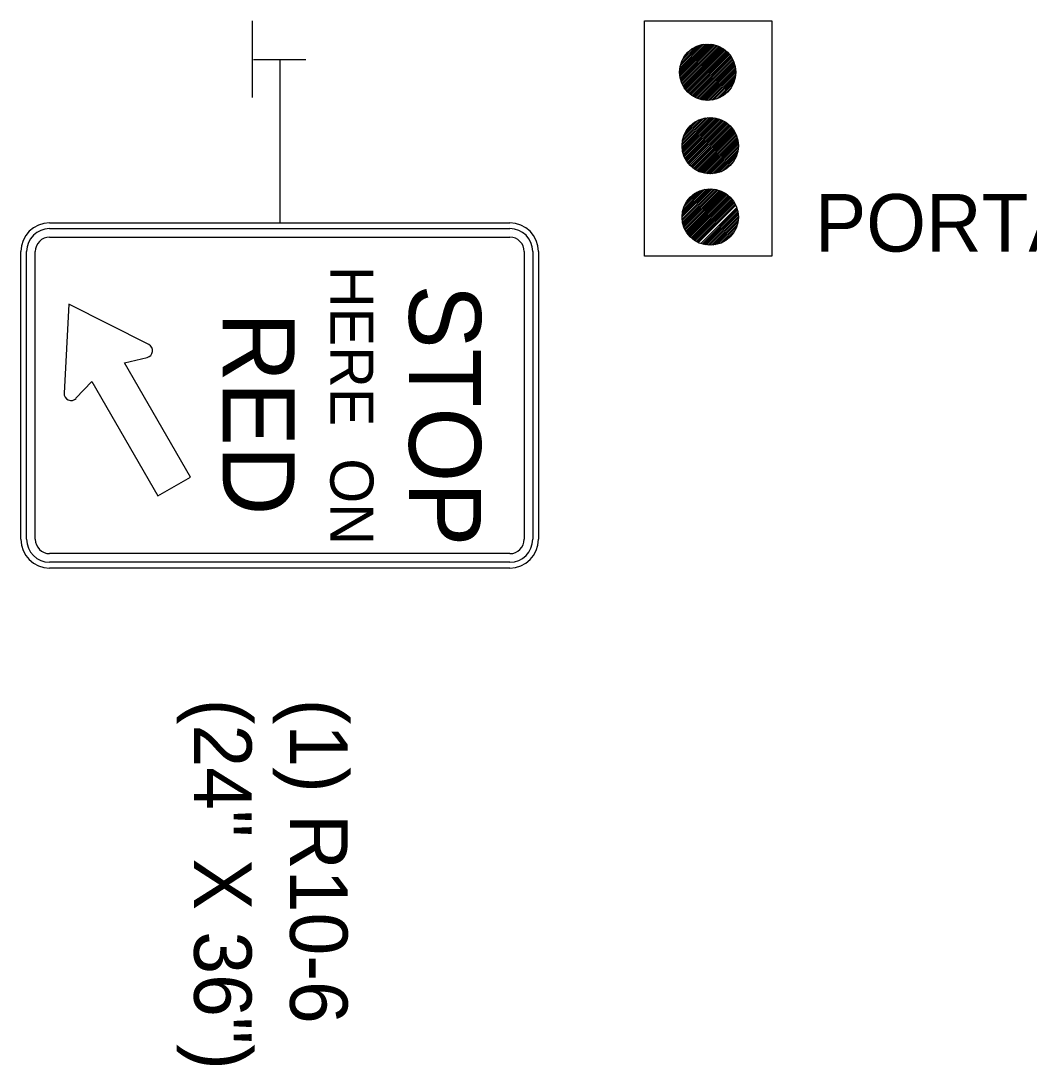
# Model space of a CAD drawing. Extents: x 1925873 to 1930787, y 596452 to 599617.
# Drawn here: x 1928229 to 1928334.2, y 597291.7 to 597400.6 of the extents above; entities that cross this region are included whole.
import ezdxf

# ---------------------------------------------------------------- set-up
doc = ezdxf.new("R2010")
doc.units = 0
for name, color, linetype in [('Default', 7, 'Continuous'), ('P_TC_Signs_Permanent', 7, 'Continuous'), ('R_Border', 7, 'Continuous')]:
    doc.layers.add(name, color=color, linetype=linetype)

msp = doc.modelspace()

# ---------------------------------------------------------------- linework, layer by layer
at = {"layer": 'Default'}
for p, q in [((1928253.15, 597392.62), (1928253.15, 597400.62)), ((1928297.7, 597395.14), (1928300.77, 597398.21)), ((1928297.7, 597395.31), (1928300.59, 597398.21)), ((1928297.7, 597395.5), (1928300.4, 597398.2)), ((1928297.71, 597394.97), (1928300.94, 597398.2)), ((1928297.73, 597394.81), (1928301.1, 597398.18)), ((1928297.73, 597395.71), (1928300.2, 597398.18)), ((1928297.76, 597394.66), (1928301.25, 597398.15)), ((1928297.77, 597395.93), (1928299.98, 597398.14)), ((1928297.8, 597394.51), (1928301.4, 597398.11)), ((1928297.84, 597394.37), (1928301.54, 597398.07)), ((1928297.84, 597396.18), (1928299.73, 597398.07)), ((1928297.88, 597394.24), (1928301.67, 597398.02)), ((1928297.94, 597394.11), (1928301.8, 597397.97)), ((1928297.95, 597396.48), (1928299.43, 597397.96)), ((1928297.99, 597393.98), (1928301.93, 597397.92)), ((1928298.05, 597393.86), (1928302.04, 597397.85)), ((1928298.12, 597393.75), (1928302.16, 597397.79)), ((1928298.17, 597396.87), (1928299.03, 597397.74)), ((1928298.19, 597393.64), (1928302.27, 597397.72)), ((1928298.26, 597393.53), (1928302.38, 597397.64)), ((1928253.27, 597396.6), (1928258.73, 597396.6)), ((1928298.34, 597393.43), (1928302.48, 597397.56)), ((1928298.43, 597393.33), (1928302.58, 597397.48)), ((1928298.51, 597393.24), (1928302.67, 597397.4)), ((1928298.6, 597393.15), (1928302.76, 597397.31)), ((1928298.7, 597393.06), (1928302.85, 597397.21)), ((1928298.8, 597392.98), (1928302.93, 597397.11)), ((1928298.9, 597392.9), (1928303.01, 597397.01)), ((1928299, 597392.82), (1928303.08, 597396.9)), ((1928299.11, 597392.75), (1928303.15, 597396.79)), ((1928299.23, 597392.69), (1928303.22, 597396.68)), ((1928299.35, 597392.63), (1928303.28, 597396.56)), ((1928299.47, 597392.57), (1928303.34, 597396.43)), ((1928299.6, 597392.52), (1928303.39, 597396.31)), ((1928299.74, 597392.47), (1928303.44, 597396.17)), ((1928299.88, 597392.43), (1928303.48, 597396.03)), ((1928300.02, 597392.39), (1928303.51, 597395.89)), ((1928300.17, 597392.37), (1928303.54, 597395.73)), ((1928300.33, 597392.35), (1928303.56, 597395.57)), ((1928300.5, 597392.33), (1928303.58, 597395.41)), ((1928300.68, 597392.33), (1928303.58, 597395.23)), ((1928300.87, 597392.34), (1928303.57, 597395.04)), ((1928301.07, 597392.36), (1928303.55, 597394.83)), ((1928301.3, 597392.41), (1928303.5, 597394.61)), ((1928301.55, 597392.47), (1928303.43, 597394.36)), ((1928301.84, 597392.59), (1928303.32, 597394.06)), ((1928302.24, 597392.81), (1928303.1, 597393.66)), ((1928297.96, 597387.65), (1928300.86, 597390.55)), ((1928297.97, 597387.48), (1928301.04, 597390.55)), ((1928297.97, 597387.84), (1928300.67, 597390.54)), ((1928297.98, 597387.31), (1928301.21, 597390.54)), ((1928298, 597387.15), (1928301.37, 597390.52)), ((1928298, 597388.05), (1928300.47, 597390.52)), ((1928298.03, 597387), (1928301.52, 597390.49)), ((1928298.04, 597388.27), (1928300.25, 597390.48)), ((1928298.06, 597386.85), (1928301.67, 597390.45)), ((1928298.11, 597386.71), (1928301.81, 597390.41)), ((1928298.11, 597388.52), (1928300, 597390.41)), ((1928298.15, 597386.58), (1928301.94, 597390.37)), ((1928298.2, 597386.45), (1928302.07, 597390.31)), ((1928298.22, 597388.82), (1928299.7, 597390.3)), ((1928298.26, 597386.32), (1928302.19, 597390.26)), ((1928298.32, 597386.2), (1928302.31, 597390.2)), ((1928298.39, 597386.09), (1928302.43, 597390.13)), ((1928298.44, 597389.21), (1928299.3, 597390.08)), ((1928298.46, 597385.98), (1928302.54, 597390.06)), ((1928298.53, 597385.87), (1928302.65, 597389.98)), ((1928298.61, 597385.77), (1928302.75, 597389.91)), ((1928298.69, 597385.67), (1928302.85, 597389.82)), ((1928298.78, 597385.58), (1928302.94, 597389.74)), ((1928298.87, 597385.49), (1928303.03, 597389.65)), ((1928298.97, 597385.4), (1928303.12, 597389.55)), ((1928299.06, 597385.32), (1928303.2, 597389.45)), ((1928299.17, 597385.24), (1928303.28, 597389.35)), ((1928299.27, 597385.16), (1928303.35, 597389.24)), ((1928299.38, 597385.09), (1928303.42, 597389.13)), ((1928299.5, 597385.03), (1928303.49, 597389.02)), ((1928299.62, 597384.97), (1928303.55, 597388.9)), ((1928299.74, 597384.91), (1928303.61, 597388.78)), ((1928299.87, 597384.86), (1928303.66, 597388.65)), ((1928300.01, 597384.81), (1928303.71, 597388.51)), ((1928300.15, 597384.77), (1928303.75, 597388.37)), ((1928300.29, 597384.74), (1928303.78, 597388.23)), ((1928300.44, 597384.71), (1928303.81, 597388.07)), ((1928300.6, 597384.69), (1928303.83, 597387.91)), ((1928300.77, 597384.67), (1928303.84, 597387.75)), ((1928300.95, 597384.67), (1928303.85, 597387.57)), ((1928301.14, 597384.68), (1928303.84, 597387.38)), ((1928301.34, 597384.7), (1928303.81, 597387.17)), ((1928301.57, 597384.75), (1928303.77, 597386.95)), ((1928301.82, 597384.82), (1928303.7, 597386.7)), ((1928302.11, 597384.93), (1928303.59, 597386.4)), ((1928302.51, 597385.15), (1928303.37, 597386.01)), ((1928297.96, 597380.14), (1928300.94, 597383.11)), ((1928297.97, 597379.96), (1928301.12, 597383.11)), ((1928297.97, 597380.32), (1928300.76, 597383.11)), ((1928297.98, 597380.52), (1928300.56, 597383.09)), ((1928297.99, 597379.8), (1928301.28, 597383.09)), ((1928298.01, 597379.64), (1928301.44, 597383.07)), ((1928298.02, 597380.73), (1928300.35, 597383.06)), ((1928298.04, 597379.49), (1928301.59, 597383.03)), ((1928298.07, 597380.97), (1928300.11, 597383.01)), ((1928298.08, 597379.35), (1928301.73, 597383)), ((1928298.13, 597379.21), (1928301.87, 597382.95)), ((1928298.16, 597381.24), (1928299.84, 597382.91)), ((1928298.17, 597379.08), (1928302, 597382.9)), ((1928298.23, 597378.95), (1928302.13, 597382.85)), ((1928298.29, 597378.83), (1928302.25, 597382.79)), ((1928298.32, 597381.58), (1928299.5, 597382.76)), ((1928298.35, 597378.71), (1928302.37, 597382.73)), ((1928298.42, 597378.6), (1928302.48, 597382.66)), ((1928298.49, 597378.49), (1928302.59, 597382.59)), ((1928298.57, 597378.39), (1928302.69, 597382.51)), ((1928298.65, 597378.29), (1928302.79, 597382.43)), ((1928298.73, 597378.19), (1928302.89, 597382.35)), ((1928298.82, 597378.1), (1928302.98, 597382.26)), ((1928298.91, 597378.01), (1928303.07, 597382.17)), ((1928299.01, 597377.92), (1928303.15, 597382.07)), ((1928299.11, 597377.84), (1928303.24, 597381.97)), ((1928299.21, 597377.77), (1928303.31, 597381.87)), ((1928299.32, 597377.69), (1928303.38, 597381.76)), ((1928299.43, 597377.63), (1928303.45, 597381.64)), ((1928299.55, 597377.56), (1928303.52, 597381.53)), ((1928299.67, 597377.5), (1928303.58, 597381.41)), ((1928299.93, 597377.4), (1928303.68, 597381.15)), ((1928300.07, 597377.35), (1928303.73, 597381.01)), ((1928300.21, 597377.32), (1928303.76, 597380.87)), ((1928300.36, 597377.28), (1928303.8, 597380.72)), ((1928300.51, 597377.26), (1928303.82, 597380.57)), ((1928300.68, 597377.24), (1928303.84, 597380.4)), ((1928300.85, 597377.23), (1928303.85, 597380.23)), ((1928301.03, 597377.23), (1928303.84, 597380.05)), ((1928301.23, 597377.25), (1928303.83, 597379.85)), ((1928301.44, 597377.28), (1928303.8, 597379.64)), ((1928301.67, 597377.33), (1928303.75, 597379.4)), ((1928301.94, 597377.42), (1928303.66, 597379.14)), ((1928302.27, 597377.57), (1928303.51, 597378.81)), ((1928302.84, 597377.96), (1928303.12, 597378.24))]:
    msp.add_line(p, q, dxfattribs=at)
msp.add_lwpolyline([(1928294.06, 597400.62), (1928307.35, 597400.62), (1928307.35, 597376.09), (1928294.06, 597376.09)], close=True, dxfattribs=at)
for centre in [(1928300.64, 597395.27), (1928300.91, 597387.61), (1928300.91, 597380.17)]:
    msp.add_circle(centre, 2.94, dxfattribs=at)
at = {"layer": 'P_TC_Signs_Permanent'}
for p, q in [((1928232, 597379.57), (1928280, 597379.57)), ((1928232, 597378.97), (1928280, 597378.97)), ((1928232, 597378.07), (1928280, 597378.07)), ((1928229, 597346.57), (1928229, 597376.57)), ((1928229.6, 597346.57), (1928229.6, 597376.57)), ((1928230.5, 597346.57), (1928230.5, 597376.57)), ((1928281.5, 597376.57), (1928281.5, 597346.57)), ((1928282.4, 597376.57), (1928282.4, 597346.57)), ((1928283, 597376.57), (1928283, 597346.57)), ((1928280, 597345.07), (1928232, 597345.07)), ((1928280, 597344.17), (1928232, 597344.17)), ((1928280, 597343.57), (1928232, 597343.57))]:
    msp.add_line(p, q, dxfattribs=at)
for points in [[(1928242.34, 597366.87), (1928234.02, 597371.07), (1928233.51, 597361.8)], [(1928234.75, 597361.27), (1928236.4, 597363.01), (1928243.28, 597351.09), (1928246.69, 597353.06), (1928239.81, 597364.98), (1928242.18, 597365.53)]]:
    msp.add_lwpolyline(points, dxfattribs=at)
for centre, radius, start, end in [((1928232, 597376.57), 3, 90, 180), ((1928280, 597376.57), 3, 360, 90), ((1928232, 597376.57), 2.4, 90, 180), ((1928232, 597376.57), 1.5, 90, 180), ((1928280, 597376.57), 2.4, 360, 90), ((1928280, 597376.57), 1.5, 360, 90), ((1928242.01, 597366.23), 0.72, 283.0349, 63.2286), ((1928234.23, 597361.76), 0.72, 176.857, 316.6377), ((1928232, 597346.57), 3, 180, 270), ((1928232, 597346.57), 2.4, 180, 270), ((1928232, 597346.57), 1.5, 180, 270), ((1928280, 597346.57), 3, 270, 360), ((1928280, 597346.57), 2.4, 270, 360), ((1928280, 597346.57), 1.5, 270, 360)]:
    msp.add_arc(centre, radius, start, end, dxfattribs=at)
at = {"layer": 'R_Border'}
msp.add_line((1928256, 597396.6), (1928256, 597379.57), dxfattribs=at)

# ---------------------------------------------------------------- texts
at = {"layer": 'Default'}
msp.add_text('PORTABLE TRAFFIC SIGNAL SYSTEM', height=5.9996, rotation=360, dxfattribs=at).set_placement((1928311.83, 597376.57))
at = {"layer": 'P_TC_Signs_Permanent'}
for s, height, p in [('HERE  ON', 4.5, (1928261.28, 597375.07)), ('STOP', 7.5, (1928269.5, 597373.14)), ('RED', 7.5, (1928250.06, 597370.24))]:
    msp.add_text(s, height=height, rotation=270, dxfattribs=at).set_placement(p)
at = {"layer": 'R_Border'}
for s, height, p in [('(24" X 36")', 5.9996, (1928247.07, 597329.94)), ('(1) R10-6', 6, (1928257.08, 597329.94))]:
    msp.add_text(s, height=height, rotation=270, dxfattribs=at).set_placement(p)

doc.saveas('drawing.dxf')
